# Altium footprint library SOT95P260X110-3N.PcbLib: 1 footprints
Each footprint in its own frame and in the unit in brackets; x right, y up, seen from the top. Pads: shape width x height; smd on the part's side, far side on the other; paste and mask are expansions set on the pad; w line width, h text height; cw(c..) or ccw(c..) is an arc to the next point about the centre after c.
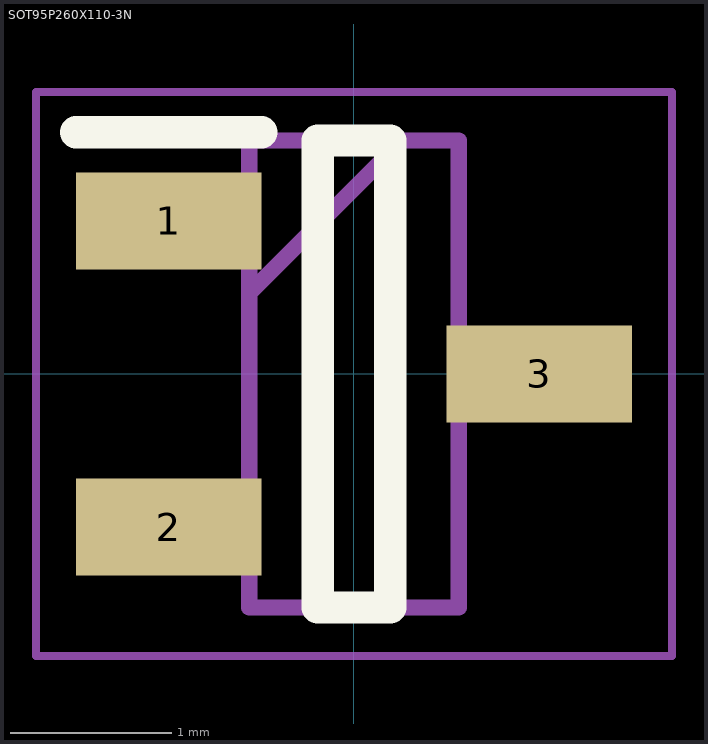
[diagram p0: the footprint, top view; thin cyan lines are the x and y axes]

## SOT95P260X110-3N [mm]
pads (3):
  rect 1.15x0.6 smd: 1(-1.15,0.95) 2(-1.15,-0.95) 3(1.15,0)
Top Overlay:
  lines w0.2: -1.725,1.5 -0.575,1.5 ; -0.225,-1.45 0.225,-1.45 0.225,1.45 -0.225,1.45 -0.225,-1.45
Mechanical 15:
  lines w0.1: -0.65,0.5 0.3,1.45 ; -0.65,-1.45 0.65,-1.45 0.65,1.45 -0.65,1.45 -0.65,-1.45
Mechanical 20:
  lines w0.05: -1.975,-1.75 1.975,-1.75 1.975,1.75 -1.975,1.75 -1.975,-1.75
